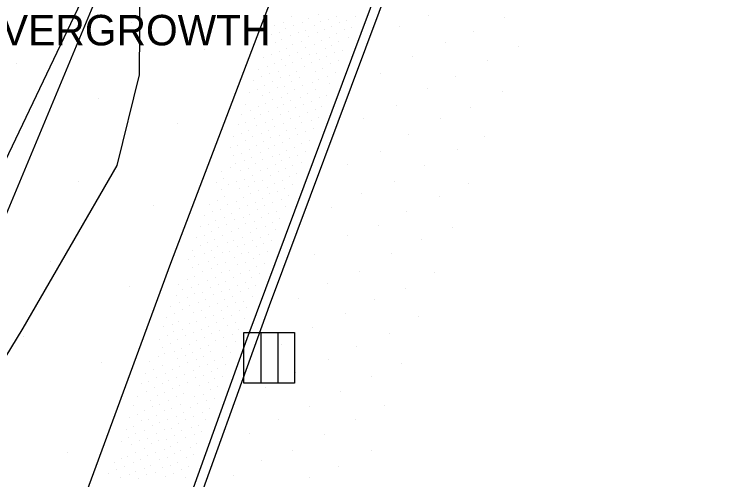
# Model space of a CAD drawing. Extents: x 1729983 to 1730242, y 468641 to 469019.
# Drawn here: x 1730086.95 to 1730129, y 468913 to 468940.46 of the extents above; entities that cross this region are included whole.
import ezdxf

# ---------------------------------------------------------------- set-up
doc = ezdxf.new("R2010")
doc.units = 0
for name, color, linetype in [('Default', 7, 'Continuous'), ('S_Curb_Type_1', 7, 'Continuous'), ('S_Drainage_CB', 7, 'Continuous'), ('S_Ground_SpotElevation', 7, 'Continuous'), ('S_Roadway_Edge_Pavement', 7, 'Continuous'), ('S_Roadway_Sidewalks', 7, 'Continuous'), ('S_Text', 7, 'Continuous'), ('S_Trees_Bush_Line', 7, 'Continuous'), ('S_Utilities_AG_Communications', 7, 'Continuous'), ('S_Utilities_GuyWire3', 7, 'Continuous')]:
    doc.layers.add(name, color=color, linetype=linetype)

# ---------------------------------------------------------------- blocks, each defined once
blk = doc.blocks.new('POINT_DISPLAY')
at = {"layer": 'Default'}
blk.add_line((0, 0), (0, 0), dxfattribs=at)

msp = doc.modelspace()

# ---------------------------------------------------------------- linework, layer by layer
at = {"layer": 'S_Curb_Type_1'}
msp.add_lwpolyline([(1730127.344, 469003.745), (1730128.313, 469003.209), (1730129.005, 469001.957), (1730128.001, 468995.343), (1730121.966, 468978.7), (1730114.875, 468959.641), (1730107.952, 468940.794), (1730100.667, 468921.305), (1730089.464, 468890.124), (1730080.18, 468865.229), (1730072.814, 468845.368), (1730066.167, 468827.336), (1730059.271, 468808.011), (1730050.413, 468784.194), (1730032.961, 468736.85), (1730026.597, 468719.521), (1730017.926, 468696.116)], dxfattribs=at)
at = {"layer": 'S_Drainage_CB'}
for p, q in [((1730101.503, 468921.692), (1730101.503, 468918.698)), ((1730102.501, 468921.692), (1730102.501, 468918.698))]:
    msp.add_line(p, q, dxfattribs=at)
msp.add_lwpolyline([(1730100.505, 468921.692), (1730103.499, 468921.692), (1730103.499, 468918.698), (1730100.505, 468918.698)], close=True, dxfattribs=at)
at = {"layer": 'S_Roadway_Edge_Pavement'}
msp.add_lwpolyline([(1730128.624, 468995.344), (1730122.317, 468978.183), (1730114.717, 468957.613), (1730108.465, 468940.563), (1730101.987, 468923.258), (1730100.18, 468918.245), (1730089.85, 468889.621), (1730080.624, 468864.761), (1730073.33, 468845.31), (1730066.507, 468826.616), (1730059.612, 468807.458), (1730050.88, 468783.514), (1730042.113, 468759.912), (1730034.557, 468739.828), (1730031.891, 468732.687), (1730026.743, 468718.512), (1730018.434, 468695.905)], dxfattribs=at)
at = {"layer": 'S_Roadway_Sidewalks'}
msp.add_lwpolyline([(1730119.084, 469000.57), (1730119.448, 468999.332), (1730120.056, 468996.986), (1730120.498, 468995.123), (1730119.297, 468990.738), (1730114.901, 468976.742), (1730109.15, 468959.847), (1730103.637, 468945.339), (1730096.174, 468925.752), (1730091.001, 468911.699), (1730089.34, 468910.169), (1730081.674, 468911.604)], dxfattribs=at)
at = {"layer": 'S_Trees_Bush_Line'}
msp.add_lwpolyline([(1730059.491, 468966.653), (1730069.864, 468958.481), (1730078.631, 468952.373), (1730087.606, 468947.904), (1730094.366, 468942.3), (1730094.314, 468936.887), (1730092.999, 468931.526), (1730087.455, 468921.933), (1730084.021, 468916.346), (1730080.816, 468914.539)], dxfattribs=at)
at = {"layer": 'S_Utilities_AG_Communications'}
msp.add_lwpolyline([(1730120.945, 469004.632), (1730097.184, 468954.408), (1730085.556, 468926.546), (1730082.304, 468910.964), (1730034.658, 468781.323), (1729998.254, 468703.261)], dxfattribs=at)
at = {"layer": 'S_Utilities_GuyWire3'}
msp.add_lwpolyline([(1730083.167, 468925.031), (1730097.184, 468954.408)], dxfattribs=at)

# ---------------------------------------------------------------- block references
at = {"layer": 'S_Ground_SpotElevation'}
for p in [(1730103.329, 468940.307), (1730104.916, 468940.447), (1730105.942, 468940.339), (1730107.084, 468940.31), (1730111.408, 468940.355), (1730115.9, 468940.287), (1730093.893, 468939.975), (1730102.318, 468939.805), (1730102.818, 468939.993), (1730103.447, 468939.776), (1730103.94, 468939.981), (1730104.341, 468940.183), (1730104.644, 468939.789), (1730105.033, 468940.039), (1730105.496, 468940.156), (1730106.156, 468939.959), (1730106.586, 468940.098), (1730102.596, 468939.369), (1730102.963, 468939.608), (1730103.741, 468939.364), (1730104.117, 468939.514), (1730104.844, 468939.361), (1730105.283, 468939.531), (1730105.697, 468939.715), (1730106.439, 468939.53), (1730106.88, 468939.671), (1730109.697, 468939.718), (1730114.085, 468939.431), (1730102.107, 468939.246), (1730102.738, 468938.986), (1730103.243, 468939.184), (1730104.321, 468939.129), (1730105.538, 468939.068), (1730105.954, 468939.323), (1730106.651, 468939.065), (1730101.909, 468938.587), (1730102.387, 468938.766), (1730103.377, 468938.686), (1730103.874, 468938.864), (1730104.642, 468938.667), (1730105.059, 468938.924), (1730105.674, 468938.626), (1730106.087, 468938.831), (1730112.39, 468938.808), (1730116.726, 468938.555), (1730098.159, 468938.395), (1730102.58, 468938.262), (1730103.026, 468938.43), (1730103.639, 468938.203), (1730104.141, 468938.476), (1730104.787, 468938.15), (1730105.296, 468938.442), (1730105.878, 468938.194), (1730106.316, 468938.347), (1730101.632, 468937.905), (1730102.13, 468938.063), (1730102.722, 468937.787), (1730103.193, 468938.009), (1730103.929, 468937.834), (1730104.372, 468938.061), (1730104.953, 468937.765), (1730105.371, 468937.953), (1730106.105, 468937.72), (1730110.431, 468937.946), (1730114.891, 468937.721), (1730087.091, 468937.566), (1730101.891, 468937.365), (1730102.292, 468937.547), (1730102.955, 468937.448), (1730103.345, 468937.6), (1730104.091, 468937.348), (1730104.522, 468937.6), (1730105.157, 468937.255), (1730105.624, 468937.567), (1730101.344, 468937.194), (1730102.041, 468936.942), (1730102.54, 468937.103), (1730103.176, 468936.86), (1730103.588, 468937.104), (1730104.755, 468937.104), (1730105.891, 468937.017), (1730108.577, 468936.958), (1730101.092, 468936.531), (1730101.548, 468936.764), (1730102.219, 468936.513), (1730102.665, 468936.71), (1730103.342, 468936.462), (1730103.805, 468936.711), (1730104.561, 468936.443), (1730104.913, 468936.592), (1730105.42, 468936.794), (1730113.017, 468936.774), (1730101.292, 468936.044), (1730101.735, 468936.283), (1730102.479, 468936.115), (1730102.923, 468936.179), (1730103.509, 468936.036), (1730103.971, 468936.235), (1730104.702, 468935.99), (1730105.557, 468936.359), (1730111.338, 468936.09), (1730100.849, 468935.82), (1730101.613, 468935.665), (1730102.001, 468935.85), (1730103.059, 468935.779), (1730104.267, 468935.803), (1730105.36, 468935.692), (1730115.76, 468935.925), (1730091.92, 468935.477), (1730100.604, 468935.149), (1730101.781, 468935.174), (1730102.187, 468935.437), (1730102.693, 468935.538), (1730103.272, 468935.385), (1730103.842, 468935.529), (1730104.029, 468935.154), (1730104.509, 468935.336), (1730104.971, 468935.567), (1730100.908, 468934.801), (1730101.34, 468935.005), (1730101.982, 468934.727), (1730102.472, 468934.944), (1730102.847, 468935.14), (1730103.566, 468934.952), (1730104.716, 468934.866), (1730105.107, 468935.038), (1730109.494, 468935.061), (1730113.862, 468934.982), (1730100.38, 468934.562), (1730101.114, 468934.327), (1730101.511, 468934.569), (1730102.668, 468934.539), (1730103.139, 468934.693), (1730103.81, 468934.424), (1730104.26, 468934.649), (1730104.92, 468934.396), (1730107.559, 468934.31), (1730112.091, 468934.331), (1730096.576, 468934.024), (1730100.167, 468933.934), (1730100.626, 468934.044), (1730101.246, 468933.894), (1730101.79, 468934.088), (1730102.201, 468934.272), (1730102.864, 468934.018), (1730103.268, 468934.295), (1730103.921, 468934.052), (1730104.478, 468934.165), (1730100.798, 468933.612), (1730101.945, 468933.616), (1730102.337, 468933.833), (1730103.009, 468933.603), (1730103.55, 468933.716), (1730104.153, 468933.546), (1730104.594, 468933.736), (1730099.863, 468933.241), (1730100.383, 468933.395), (1730101.016, 468933.238), (1730101.527, 468933.424), (1730102.08, 468933.184), (1730102.62, 468933.32), (1730103.203, 468933.129), (1730103.661, 468933.346), (1730110.225, 468933.371), (1730114.693, 468933.234), (1730100.153, 468932.699), (1730100.585, 468933.017), (1730101.27, 468932.721), (1730101.684, 468932.952), (1730102.335, 468932.736), (1730102.766, 468932.918), (1730103.507, 468932.625), (1730103.895, 468932.844), (1730104.403, 468933.011), (1730099.713, 468932.586), (1730100.344, 468932.269), (1730100.852, 468932.499), (1730101.506, 468932.308), (1730101.941, 468932.556), (1730103.016, 468932.407), (1730104.126, 468932.34), (1730108.577, 468932.376), (1730113.112, 468932.462), (1730099.879, 468932.142), (1730100.518, 468931.855), (1730100.96, 468932.031), (1730101.612, 468931.879), (1730102.183, 468932.056), (1730102.606, 468932.201), (1730102.738, 468931.838), (1730103.172, 468931.994), (1730103.661, 468932.138), (1730099.694, 468931.419), (1730100.022, 468931.67), (1730101.169, 468931.63), (1730102.344, 468931.588), (1730103.389, 468931.532), (1730103.904, 468931.729), (1730106.621, 468931.594), (1730111.186, 468931.513), (1730099.158, 468931.165), (1730100.331, 468931.214), (1730100.78, 468931.348), (1730100.985, 468930.967), (1730101.458, 468931.214), (1730101.9, 468931.335), (1730102.093, 468930.947), (1730102.53, 468931.157), (1730102.977, 468931.355), (1730103.594, 468931.092), (1730090.764, 468930.588), (1730098.871, 468930.523), (1730099.318, 468930.74), (1730100.083, 468930.574), (1730100.566, 468930.702), (1730101.145, 468930.568), (1730101.592, 468930.65), (1730102.802, 468930.636), (1730103.179, 468930.898), (1730109.41, 468930.618), (1730099.17, 468930.123), (1730099.616, 468930.4), (1730100.241, 468930.151), (1730100.75, 468930.323), (1730101.883, 468930.264), (1730102.28, 468930.478), (1730102.929, 468930.169), (1730103.39, 468930.437), (1730113.747, 468930.485), (1730099.36, 468929.713), (1730100.903, 468929.888), (1730101.375, 468930.041), (1730102.024, 468929.864), (1730102.505, 468930.02), (1730103.118, 468929.758), (1730107.458, 468929.856), (1730112.064, 468929.731), (1730098.93, 468929.457), (1730099.517, 468929.263), (1730100.039, 468929.435), (1730100.489, 468929.648), (1730101.16, 468929.361), (1730101.592, 468929.58), (1730102.192, 468929.324), (1730102.738, 468929.557), (1730095.149, 468929.171), (1730098.453, 468929.247), (1730099.144, 468928.958), (1730100.219, 468929.006), (1730100.726, 468929.15), (1730101.299, 468928.918), (1730101.744, 468929.151), (1730102.42, 468928.845), (1730102.967, 468929.102), (1730105.7, 468929.055), (1730098.185, 468928.562), (1730098.631, 468928.799), (1730099.333, 468928.495), (1730099.798, 468928.722), (1730100.454, 468928.49), (1730100.824, 468928.666), (1730101.536, 468928.462), (1730101.958, 468928.684), (1730110.121, 468928.831), (1730098.394, 468928.079), (1730098.851, 468928.296), (1730099.488, 468928.077), (1730099.939, 468928.323), (1730100.59, 468928.086), (1730101.109, 468928.231), (1730102.183, 468928.197), (1730102.617, 468928.409), (1730097.931, 468927.911), (1730098.583, 468927.627), (1730099.024, 468927.865), (1730099.76, 468927.667), (1730100.186, 468927.839), (1730100.901, 468927.588), (1730101.253, 468927.822), (1730101.77, 468927.957), (1730102.386, 468927.747), (1730108.476, 468927.977), (1730112.838, 468927.878), (1730097.702, 468927.31), (1730098.155, 468927.435), (1730098.777, 468927.174), (1730099.229, 468927.383), (1730100.395, 468927.312), (1730101.495, 468927.316), (1730101.981, 468927.489), (1730106.589, 468927.403), (1730110.971, 468927.177), (1730097.931, 468926.837), (1730098.354, 468926.989), (1730098.965, 468926.737), (1730099.512, 468927.022), (1730099.905, 468927.115), (1730100.55, 468926.885), (1730101.017, 468927.097), (1730101.651, 468926.915), (1730102.107, 468927.094), (1730097.47, 468926.538), (1730098.17, 468926.354), (1730098.562, 468926.543), (1730099.227, 468926.376), (1730099.638, 468926.474), (1730100.149, 468926.729), (1730100.384, 468926.335), (1730100.783, 468926.422), (1730101.244, 468926.735), (1730101.921, 468926.465), (1730109.243, 468926.319), (1730097.232, 468925.998), (1730097.586, 468926.163), (1730098.75, 468926.12), (1730099.94, 468926.117), (1730101.069, 468926.061), (1730101.397, 468926.271), (1730104.689, 468926.284), (1730089.085, 468925.889), (1730097.478, 468925.516), (1730097.823, 468925.724), (1730098.394, 468925.887), (1730098.953, 468925.677), (1730099.403, 468925.83), (1730100.11, 468925.688), (1730100.618, 468925.803), (1730101.235, 468925.565), (1730101.723, 468925.745), (1730098.038, 468925.279), (1730098.595, 468925.461), (1730099.161, 468925.236), (1730099.643, 468925.331), (1730100.288, 468925.137), (1730100.815, 468925.37), (1730101.453, 468925.157), (1730107.302, 468925.299), (1730111.762, 468925.216), (1730097.202, 468924.813), (1730097.574, 468925.008), (1730098.343, 468924.757), (1730098.8, 468924.957), (1730099.397, 468924.688), (1730099.917, 468924.916), (1730100.589, 468924.658), (1730100.97, 468924.953), (1730093.736, 468924.376), (1730096.668, 468924.542), (1730097.399, 468924.339), (1730097.832, 468924.509), (1730098.506, 468924.351), (1730098.998, 468924.513), (1730099.677, 468924.241), (1730100.124, 468924.47), (1730100.748, 468924.259), (1730101.215, 468924.458), (1730105.445, 468924.6), (1730110.019, 468924.286), (1730096.507, 468923.887), (1730096.873, 468924.195), (1730097.576, 468923.963), (1730098.052, 468924.064), (1730098.723, 468923.91), (1730099.17, 468924.101), (1730099.859, 468923.826), (1730100.275, 468924.089), (1730101.011, 468923.792), (1730096.712, 468923.45), (1730097.168, 468923.74), (1730097.831, 468923.437), (1730098.265, 468923.658), (1730098.973, 468923.417), (1730099.34, 468923.611), (1730100.036, 468923.426), (1730100.486, 468923.532), (1730103.704, 468923.699), (1730108.198, 468923.607), (1730096.192, 468923.222), (1730096.862, 468923.028), (1730097.311, 468923.257), (1730098.008, 468923.002), (1730098.451, 468923.248), (1730099.2, 468922.954), (1730099.559, 468923.245), (1730100.238, 468922.993), (1730100.647, 468923.15), (1730095.912, 468922.585), (1730096.381, 468922.812), (1730097.533, 468922.858), (1730098.254, 468922.598), (1730098.696, 468922.692), (1730099.787, 468922.684), (1730106.488, 468922.782), (1730110.783, 468922.63), (1730096.26, 468922.171), (1730096.624, 468922.342), (1730097.295, 468922.2), (1730097.721, 468922.329), (1730098.905, 468922.268), (1730099.304, 468922.52), (1730099.552, 468922.127), (1730099.991, 468922.257), (1730100.51, 468922.491), (1730095.755, 468922.018), (1730096.374, 468921.735), (1730096.861, 468921.84), (1730097.519, 468921.698), (1730098.001, 468921.874), (1730098.441, 468922.06), (1730099.076, 468921.785), (1730100.187, 468921.833), (1730104.564, 468921.992), (1730087.464, 468921.463), (1730095.54, 468921.293), (1730096.007, 468921.48), (1730097.062, 468921.486), (1730098.194, 468921.41), (1730098.598, 468921.653), (1730099.286, 468921.4), (1730099.807, 468921.541), (1730109.104, 468921.606), (1730096.158, 468921.053), (1730096.611, 468921.259), (1730097.292, 468920.981), (1730097.729, 468921.223), (1730098.403, 468920.931), (1730098.822, 468921.221), (1730099.483, 468920.864), (1730100.026, 468921.166), (1730102.719, 468920.982), (1730107.153, 468920.862), (1730095.693, 468920.782), (1730096.399, 468920.536), (1730096.843, 468920.755), (1730097.491, 468920.518), (1730097.942, 468920.737), (1730098.556, 468920.544), (1730099.684, 468920.514), (1730095.44, 468920.251), (1730095.836, 468920.42), (1730096.598, 468920.137), (1730097.035, 468920.301), (1730097.677, 468920.067), (1730098.139, 468920.27), (1730098.776, 468920.022), (1730099.235, 468920.21), (1730105.513, 468920.108), (1730092.12, 468919.941), (1730094.922, 468919.985), (1730095.705, 468919.721), (1730096.72, 468919.689), (1730097.172, 468919.902), (1730097.864, 468919.678), (1730098.381, 468919.791), (1730099.403, 468919.787), (1730109.781, 468919.867), (1730094.676, 468919.29), (1730095.177, 468919.486), (1730095.861, 468919.238), (1730096.295, 468919.486), (1730096.969, 468919.218), (1730097.503, 468919.452), (1730098.575, 468919.377), (1730098.969, 468919.558), (1730103.541, 468919.334), (1730094.886, 468918.822), (1730095.365, 468919.044), (1730096.072, 468918.855), (1730096.497, 468919.021), (1730097.626, 468919.007), (1730098.093, 468919.122), (1730098.747, 468918.972), (1730099.216, 468919.082), (1730108.02, 468919.084), (1730094.449, 468918.652), (1730095.215, 468918.433), (1730095.676, 468918.657), (1730096.307, 468918.378), (1730096.726, 468918.539), (1730097.165, 468918.716), (1730097.879, 468918.588), (1730098.392, 468918.735), (1730098.506, 468918.328), (1730098.931, 468918.523), (1730101.778, 468918.418), (1730094.225, 468917.918), (1730094.725, 468918.187), (1730095.375, 468917.96), (1730095.796, 468918.16), (1730096.523, 468917.924), (1730096.943, 468918.071), (1730097.573, 468917.93), (1730098.107, 468918.02), (1730106.199, 468918.187), (1730094.979, 468917.685), (1730096.027, 468917.691), (1730098.283, 468917.65), (1730098.779, 468917.817), (1730093.976, 468917.36), (1730094.625, 468917.064), (1730095.126, 468917.292), (1730095.532, 468917.441), (1730095.839, 468917.079), (1730096.25, 468917.224), (1730096.763, 468917.439), (1730097.341, 468917.261), (1730097.791, 468917.478), (1730098.483, 468917.191), (1730104.364, 468917.324), (1730108.78, 468917.366), (1730093.732, 468916.697), (1730094.217, 468916.829), (1730095.358, 468916.816), (1730096.5, 468916.72), (1730096.949, 468916.955), (1730097.509, 468916.757), (1730098.073, 468916.978), (1730094.457, 468916.478), (1730094.85, 468916.55), (1730095.497, 468916.383), (1730095.997, 468916.57), (1730096.667, 468916.289), (1730097.084, 468916.527), (1730098.242, 468916.575), (1730102.541, 468916.527), (1730107.118, 468916.549), (1730093.557, 468915.942), (1730093.997, 468916.135), (1730094.658, 468915.88), (1730095.137, 468916.218), (1730095.796, 468915.958), (1730096.248, 468916.051), (1730096.838, 468915.906), (1730097.408, 468916.081), (1730097.815, 468916.221), (1730097.978, 468915.843), (1730093.714, 468915.471), (1730094.111, 468915.754), (1730094.793, 468915.437), (1730095.365, 468915.721), (1730095.936, 468915.387), (1730096.377, 468915.63), (1730097.039, 468915.472), (1730097.585, 468915.676), (1730100.842, 468915.733), (1730105.267, 468915.697), (1730093.255, 468915.26), (1730093.894, 468915.084), (1730094.369, 468915.338), (1730095.029, 468915.112), (1730095.489, 468915.295), (1730096.18, 468914.976), (1730096.564, 468915.208), (1730097.724, 468915.114), (1730090.092, 468914.611), (1730094.081, 468914.627), (1730094.658, 468914.857), (1730095.314, 468914.615), (1730095.793, 468914.773), (1730096.41, 468914.571), (1730096.773, 468914.751), (1730097.346, 468914.924), (1730103.391, 468914.752), (1730108.056, 468914.705), (1730093.259, 468914.247), (1730093.657, 468914.391), (1730094.427, 468914.197), (1730094.826, 468914.432), (1730095.495, 468914.178), (1730095.971, 468914.339), (1730097.086, 468914.299), (1730097.531, 468914.516), (1730101.571, 468914.12), (1730092.843, 468914.013), (1730093.466, 468913.765), (1730093.969, 468914.001), (1730095.012, 468913.847), (1730095.689, 468913.713), (1730096.179, 468913.857), (1730096.568, 468914.021), (1730097.232, 468913.807), (1730106.075, 468913.806), (1730092.499, 468913.378), (1730093.007, 468913.579), (1730093.724, 468913.301), (1730094.12, 468913.512), (1730094.615, 468913.683), (1730094.755, 468913.282), (1730095.288, 468913.429), (1730096.367, 468913.395), (1730096.827, 468913.58), (1730093.192, 468913.134), (1730094.269, 468913.098), (1730095.891, 468913.22), (1730097.047, 468913.13), (1730099.908, 468913.276), (1730104.38, 468913.113)]:
    msp.add_blockref('POINT_DISPLAY', p, dxfattribs=at)

# ---------------------------------------------------------------- texts
at = {"layer": 'S_Text'}
msp.add_text('OVERGROWTH', height=1.8, dxfattribs=at).set_placement((1730084.29, 468938.62))

doc.saveas('drawing.dxf')
